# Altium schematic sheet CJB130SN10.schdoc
size 127 x 101 mm
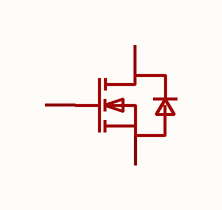
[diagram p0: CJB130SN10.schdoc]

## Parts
Q?  cjb130sn10  [TO-263-2_L9.9-W9.2-P5.08-LS15.3-TL-CW]  (value not drawn)

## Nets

Not connected (* = marked no-connect by the designer): Q? 1(G) 2(D) 3(S)

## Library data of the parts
Q? = cjb130sn10: 数量:1个N沟道;漏源电压(Vdss):100V;连续漏极电流(Id):130A;导通电阻(RDS(on)):4.3mΩ@10V;耗散功率(Pd):250W;阈值电压(Vgs(th)):3V;; Manufacturer: CJ(江苏长电/长晶); AddInBom: yes; ModelId: 1e6875e836e64c6383551dafb8071c34; ModelTransform: 602.361,389.763,0,0,0,0,48.381,0,0; Number: 1个N沟道; Drain to Source Voltage: 100V; Current - Continuous Drain(Id): 130A; Pd - Power Dissipation: 250W; Gate Threshold Voltage (Vgs(th)): 3V; Gate Charge(Qg): 91nC@10V; Input Capacitance(Ciss): 6.66nF; Reverse Transfer Capacitance (Crss@Vds): 17pF; Type: N沟道; Output Capacitance(Coss): 821pF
